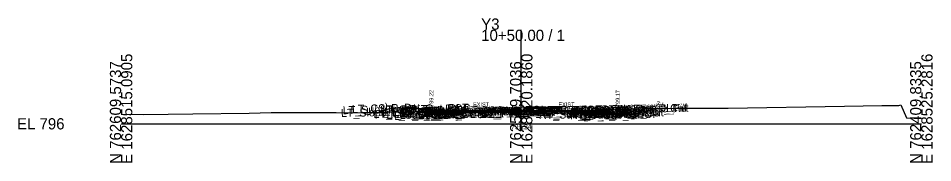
# Model space of a CAD drawing. Extents: x -26 to 203, y -10 to 3017.
# Drawn here: x -25.7 to 202.8, y 990.3 to 1026.3 of the extents above; entities that cross this region are included whole.
import ezdxf

# ---------------------------------------------------------------- set-up
doc = ezdxf.new("R2010")
doc.units = 0
for name, color, linetype in [('Default', 7, 'Continuous'), ('Exist CMT Pavement', 7, 'Continuous'), ('Exist Cross Section Cell', 7, 'Continuous'), ('Exist XS Center Line Elevation Label', 7, 'Continuous'), ('Exist XS Ground Line', 7, 'Continuous'), ('Prop CMT Conc Surface', 7, 'Continuous'), ('Prop CMT Concrete Structures', 7, 'Continuous'), ('Prop CMT Pvmt Course 1', 7, 'Continuous'), ('Prop CMT Pvmt Course 1 CG', 7, 'Continuous'), ('Prop CMT Pvmt Course 1 Wedge', 7, 'Continuous'), ('Prop CMT Pvmt Course 2', 7, 'Continuous'), ('Prop CMT Pvmt Course 2 Wedge', 7, 'Continuous'), ('Prop CMT Pvmt Course 3', 7, 'Continuous'), ('Prop CMT Pvmt Surface', 7, 'Continuous'), ('Prop CMT Pvmt Wedge Surface 1', 7, 'Continuous'), ('Prop CMT Pvmt Wedge Surface 2', 7, 'Continuous'), ('Prop CMT Pvmt Wedge Surface 3', 7, 'Continuous'), ('Prop CMT Slope Grass', 7, 'Continuous'), ('Prop CMT Subgrade Earthwork', 7, 'Continuous'), ('Prop XS Hydro Elevations', 7, 'Continuous'), ('Prop XS SE Text', 7, 'Continuous'), ('Prop XS Side Slope Text', 7, 'Continuous'), ('Scratch_Level_0', 7, 'Continuous')]:
    doc.layers.add(name, color=color, linetype=linetype)

msp = doc.modelspace()

# ---------------------------------------------------------------- linework, layer by layer
at = {"layer": 'Exist CMT Pavement'}
for points in [[(100, 1003.24), (115.2, 1003.28), (115.24, 1003.28)], [(100, 1003.24), (99.22, 1003.24), (94.27, 1003.12), (85.03, 1002.88)], [(85.03, 1002.88), (85.03, 1002.88)]]:
    msp.add_lwpolyline(points, dxfattribs=at)
at = {"layer": 'Exist Cross Section Cell'}
for p, q in [((100, 1000), (100, 1023.45)), ((0, 1000), (100, 1000)), ((100, 1000), (200, 1000))]:
    msp.add_line(p, q, dxfattribs=at)
at = {"layer": 'Exist XS Ground Line'}
msp.add_lwpolyline([(0, 1002.4), (5.63, 1002.34), (17.92, 1002.45), (32.03, 1002.66), (37.54, 1002.79), (53.71, 1002.78), (57.6, 1002.76), (60.23, 1002.8), (77.39, 1003.09), (78.8, 1003.1), (84.65, 1003.11), (85.03, 1002.88), (94.27, 1003.12), (99.22, 1003.24), (100, 1003.24), (115.24, 1003.28), (121.25, 1003.67), (122.67, 1003.73), (125.09, 1003.68), (138.73, 1003.88), (141.41, 1003.88), (151.69, 1003.91), (180.76, 1004.38), (190.13, 1004.53), (194.39, 1004.53), (194.88, 1004.73), (196.28, 1001.49), (200, 1001.31)], dxfattribs=at)
at = {"layer": 'Prop CMT Conc Surface'}
for points in [[(77.53, 1003.22), (77.53, 1003.72), (77.03, 1003.72)], [(79.53, 1003.31), (77.53, 1003.22)], [(124.13, 1003.17), (124.13, 1003.67), (124.63, 1003.67)], [(122.13, 1003.26), (124.13, 1003.17)]]:
    msp.add_lwpolyline(points, dxfattribs=at)
at = {"layer": 'Prop CMT Concrete Structures'}
for points in [[(79.53, 1003.31), (77.53, 1003.22), (77.53, 1003.72), (77.03, 1003.72)], [(77.03, 1003.72), (77.03, 1002.71), (79.53, 1002.72)], [(79.53, 1002.72), (79.53, 1003.31)], [(122.13, 1003.26), (124.13, 1003.17), (124.13, 1003.67), (124.63, 1003.67)], [(124.63, 1003.67), (124.63, 1002.66), (122.13, 1002.67)], [(122.13, 1002.67), (122.13, 1003.26)]]:
    msp.add_lwpolyline(points, dxfattribs=at)
at = {"layer": 'Prop CMT Pvmt Course 1'}
for points in [[(100, 1003.39), (79.53, 1003.31)], [(79.53, 1003.31), (79.53, 1003.06)], [(85.03, 1003.21), (100, 1003.27)], [(100, 1003.14), (100, 1003.39)], [(100, 1003.39), (122.13, 1003.26)], [(100, 1003.14), (100, 1003.39)], [(100, 1003.27), (100, 1003.14), (100, 1003.14)], [(115.24, 1003.17), (100, 1003.27)], [(100, 1003.27), (100, 1003.14), (100, 1003.14)], [(79.53, 1003.06), (85.03, 1003.08)], [(85.03, 1003.08), (85.03, 1003.21)], [(115.24, 1003.05), (115.24, 1003.17)], [(122.13, 1003.01), (115.24, 1003.05)], [(122.13, 1003.26), (122.13, 1003.01)]]:
    msp.add_lwpolyline(points, dxfattribs=at)
at = {"layer": 'Prop CMT Pvmt Course 1 CG'}
for points in [[(79.53, 1002.72), (76.53, 1002.71), (76.19, 1002.38)], [(76.19, 1002.38), (79.53, 1002.39)], [(79.53, 1002.39), (79.53, 1002.72)], [(122.13, 1002.67), (125.13, 1002.66), (125.47, 1002.32)], [(122.13, 1002.34), (122.13, 1002.67)], [(125.47, 1002.32), (122.13, 1002.34)]]:
    msp.add_lwpolyline(points, dxfattribs=at)
at = {"layer": 'Prop CMT Pvmt Course 1 Wedge'}
for points in [[(85.03, 1003.21), (94.27, 1003.24), (99.22, 1003.26), (100, 1003.27)], [(100, 1003.27), (100, 1003.24)], [(100, 1003.27), (102.51, 1003.25)], [(100, 1003.24), (100, 1003.27)], [(100, 1003.24), (99.22, 1003.24), (94.27, 1003.12), (94.15, 1003.12), (85.03, 1003.08)], [(85.03, 1003.21), (85.03, 1003.21)], [(85.03, 1003.08), (85.03, 1003.21)], [(85.03, 1003.08), (85.03, 1003.08)], [(102.51, 1003.25), (100, 1003.24)]]:
    msp.add_lwpolyline(points, dxfattribs=at)
at = {"layer": 'Prop CMT Pvmt Course 2'}
for points in [[(85.03, 1003.08), (79.53, 1003.06)], [(79.53, 1003.06), (79.53, 1002.72)], [(79.53, 1002.72), (85.03, 1002.75)], [(85.03, 1002.75), (85.03, 1003.08)], [(115.24, 1002.72), (115.24, 1003.05)], [(115.24, 1003.05), (122.13, 1003.01)], [(122.13, 1002.67), (115.24, 1002.72)], [(122.13, 1003.01), (122.13, 1002.67)]]:
    msp.add_lwpolyline(points, dxfattribs=at)
at = {"layer": 'Prop CMT Pvmt Course 2 Wedge'}
for points in [[(85.03, 1003.08), (94.15, 1003.12)], [(94.15, 1003.12), (85.03, 1002.88)], [(85.03, 1003.08), (85.03, 1003.08)], [(85.03, 1002.88), (85.03, 1003.08)], [(85.03, 1002.88), (85.03, 1002.88)]]:
    msp.add_lwpolyline(points, dxfattribs=at)
at = {"layer": 'Prop CMT Pvmt Course 3'}
for points in [[(85.03, 1002.75), (79.53, 1002.72)], [(79.53, 1002.72), (79.53, 1002.39)], [(79.53, 1002.39), (85.03, 1002.41)], [(85.03, 1002.41), (85.03, 1002.75)], [(115.24, 1002.72), (122.13, 1002.67)], [(115.24, 1002.38), (115.24, 1002.72)], [(122.13, 1002.34), (115.24, 1002.38)], [(122.13, 1002.67), (122.13, 1002.34)]]:
    msp.add_lwpolyline(points, dxfattribs=at)
at = {"layer": 'Prop CMT Pvmt Surface'}
for points in [[(100, 1003.39), (79.53, 1003.31)], [(100, 1003.39), (122.13, 1003.26)]]:
    msp.add_lwpolyline(points, dxfattribs=at)
at = {"layer": 'Prop CMT Pvmt Wedge Surface 1'}
for points in [[(79.53, 1003.06), (79.53, 1003.31)], [(100, 1003.27), (85.03, 1003.21)], [(100, 1003.27), (115.24, 1003.17)], [(85.03, 1003.08), (79.53, 1003.06)], [(85.03, 1003.21), (85.03, 1003.08)], [(115.24, 1003.17), (115.24, 1003.05)], [(115.24, 1003.05), (122.13, 1003.01)], [(122.13, 1003.01), (122.13, 1003.26)]]:
    msp.add_lwpolyline(points, dxfattribs=at)
at = {"layer": 'Prop CMT Pvmt Wedge Surface 2'}
for points in [[(79.53, 1003.06), (79.53, 1003.31)], [(100, 1003.14), (79.53, 1003.06)], [(100, 1003.14), (122.13, 1003.01)], [(122.13, 1003.01), (122.13, 1003.26)]]:
    msp.add_lwpolyline(points, dxfattribs=at)
at = {"layer": 'Prop CMT Pvmt Wedge Surface 3'}
for points in [[(79.53, 1002.72), (79.53, 1003.31)], [(100, 1002.81), (79.53, 1002.72)], [(100, 1002.81), (122.13, 1002.67)], [(122.13, 1002.67), (122.13, 1003.26)]]:
    msp.add_lwpolyline(points, dxfattribs=at)
at = {"layer": 'Prop CMT Slope Grass'}
for points in [[(77.03, 1003.72), (67.53, 1003.91), (64.42, 1002.87)], [(124.63, 1003.67), (134.13, 1003.86), (134.25, 1003.82)]]:
    msp.add_lwpolyline(points, dxfattribs=at)
at = {"layer": 'Prop CMT Subgrade Earthwork'}
for points in [[(79.53, 1002.39), (76.19, 1002.38), (74.81, 1003.76)], [(115.24, 1002.38), (115.23, 1003.28)], [(122.13, 1002.34), (125.47, 1002.32), (126.86, 1003.71)], [(85.03, 1002.41), (79.53, 1002.39)], [(85.03, 1002.41), (85.05, 1002.89)], [(115.24, 1002.38), (122.13, 1002.34)]]:
    msp.add_lwpolyline(points, dxfattribs=at)

# ---------------------------------------------------------------- texts
at = {"layer": 'Default'}
msp.add_text('-', height=0.0001, dxfattribs=at).set_placement((0, 1000))
at = {"layer": 'Exist Cross Section Cell'}
for s, p in [('Y3', (90, 1023.45)), ('10+50.00 / 1', (90, 1020.65)), ('EL 796', (-26, 998.6))]:
    msp.add_text(s, height=2.8, dxfattribs=at).set_placement(p)
for s, p in [('E 1628515.0905', (2.8, 990)), ('E 1628520.1860', (102.8, 990)), ('E 1628525.2816', (202.8, 990)), ('N 762609.5737', (0, 990)), ('N 762509.7036', (100, 990)), ('N 762409.8335', (200, 990))]:
    msp.add_text(s, height=2.8, rotation=90, dxfattribs=at).set_placement(p)
at = {"layer": 'Exist XS Center Line Elevation Label'}
msp.add_text('799.24', height=1.2, dxfattribs=at).set_placement((97.48, 998.64))
at = {"layer": 'Prop XS Hydro Elevations'}
for s, p in [('799.22', (78.03, 1004.22)), ('799.17', (124.63, 1004.17))]:
    msp.add_text(s, height=1, rotation=90, dxfattribs=at).set_placement(p)
at = {"layer": 'Prop XS SE Text'}
for rotation, p in [(0.2292, (87.97, 1004.34)), (359.6562, (109.31, 1004.33))]:
    msp.add_text('EXIST.', height=1, rotation=rotation, dxfattribs=at).set_placement(p)
at = {"layer": 'Prop XS Side Slope Text'}
for rotation, p in [(341.5668, (133.68, 1004.8)), (341.5668, (133.68, 1004.8)), (18.4332, (64.98, 1003.85))]:
    msp.add_text('3:1', height=1, rotation=rotation, dxfattribs=at).set_placement(p)
at = {"layer": 'Scratch_Level_0'}
for s, p in [('LT_Slope_Fill', (54.96, 1001.69)), ('LT_Sub_Trench_Out_DLT', (55.4, 1002.38)), ('LT_CSLP_Pnt', (57.72, 1002.71)), ('LT_CG1_Shelf_Out', (63.1, 1001.44)), ('LT_CG_Top_Face', (64.81, 1002.47)), ('LT_CG_Top_BOC', (65.33, 1002.49)), ('LT_CG_Bot_BOC', (65.36, 1001.48)), ('LT_CG_Top_Gut', (65.79, 1001.99)), ('LT_Sub_OEOP', (66.32, 1001.18)), ('LT_CG_Bot_IE', (69.46, 1001.52)), ('LT_Sub_OEOT', (69.63, 1001.19)), ('LT_PV2_OEOT', (69.72, 1001.86)), ('LT_PV3_OEOT', (69.72, 1001.53)), ('LT_PV_Sub_Tie_Out', (70.01, 1001.58)), ('LT_PV1_OEOT', (70.29, 1002.12)), ('LT_PV_OEEOP_EG', (72.6, 1001.64)), ('LT_Sub_OEEOP', (74.27, 1001.2)), ('LT_PV2_OEEOP', (74.36, 1001.87)), ('LT_PV3_OEEOP', (74.36, 1001.53)), ('LT_PV1_OEEOP', (74.93, 1002)), ('RT_PV_IEEOP_EG', (88.16, 1002.01)), ('LT_PV_IEEOP_EG', (88.21, 1002.01)), ('RT_PV2_IEEOP', (89.93, 1001.94)), ('RT_PV3_IEEOP', (89.93, 1001.61)), ('LT_PV2_IEEOP', (89.97, 1001.94)), ('LT_PV3_IEEOP', (89.97, 1001.61)), ('RT_PV1_IEEOP', (90.49, 1002.07)), ('LT_PV1_IEEOP', (90.54, 1002.08)), ('PV2_PGL', (93.93, 1002.02)), ('PV1_PGL', (94.49, 1002.28)), ('RT_PV_Sub_Tie_Out', (100.15, 1001.97)), ('RT_PV_OEEOP_EG', (102.76, 1002.03)), ('RT_Sub_OEEOP', (104.43, 1001.17)), ('RT_PV2_OEEOP', (104.53, 1001.83)), ('RT_PV3_OEEOP', (104.53, 1001.5)), ('RT_PV1_OEEOP', (105.09, 1001.97)), ('RT_Sub_Trench_Out_DLT', (107.4, 1002.32)), ('RT_CG_Top_Face', (111.37, 1002.41)), ('RT_CG1_Shelf_Out', (111.66, 1001.39)), ('RT_CG_Bot_IE', (112.02, 1001.47)), ('RT_Sub_OEOT', (112.19, 1001.14)), ('RT_PV2_OEOT', (112.28, 1001.81)), ('RT_PV3_OEOT', (112.28, 1001.48)), ('RT_CG_Top_Gut', (112.34, 1001.93)), ('RT_PV1_OEOT', (112.85, 1002.07)), ('RT_CG_Top_BOC', (112.89, 1002.43)), ('RT_CG_Bot_BOC', (112.92, 1001.42)), ('RT_Sub_OEOP', (115.55, 1001.12)), ('RT_Slope_Cut', (123.86, 1002.61)), ('RT_CSLP_Pnt', (124.28, 1002.66)), ('RT_Slope_Fill', (124.74, 1002.63))]:
    msp.add_text(s, height=2, rotation=1.1458, dxfattribs=at).set_placement(p)

doc.saveas('drawing.dxf')
